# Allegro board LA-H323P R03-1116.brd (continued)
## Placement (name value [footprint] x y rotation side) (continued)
LED2  LTW-110DC5-C_WHITE  [LED_LTW-110DC5-C_3P]  4.7 93.03 270 bottom
LK1  TAI-TECH HCB1005KF-221T15 040  [MURAT_BLM15BD601SN1D_2P]  166.73 30.75 270 top
LK2  TAI-TECH HCB1005KF-221T15 0402  [MURAT_BLM15BD601SN1D_2P]  164.7 30.87 270 top
LL2  2.2UH +-20% 1239AS-H-2R2M=P2 2A  [TAI-T_HPC252012F-1R0Y_2P]  37.95 103.45 0 bottom
LM3  DLM0NSN900HY2D_4P  [MURAT_DLM0NSN900HY2D_4P]  219.49 36.93 90 top
LM5  DLM0NSN900HY2D_4P  [MURAT_DLM0NSN900HY2D_4P]  217.67 36.93 90 top
LM6  DLM0NSN900HY2D_4P  [MURAT_DLM0NSN900HY2D_4P]  255.75 19.51 0 bottom
LM7  DLM0NSN900HY2D_4P  [MURAT_DLM0NSN900HY2D_4P]  24.92 99.33 180 bottom
LV5  PBY160808T-300Y-N 0603  [MURAT_BLM18PG300SN1D_2P]  126.27 99.16 270 top
LV6  CHILISIN PBY160808T-301Y-N 0603  [KC_FBMA-L11160808601LMA10T_2P]  126.35 95.41 270 bottom
LV7  PBY160808T-300Y-N 0603  [MURAT_BLM18PG300SN1D_2P]  130.92 111.79 90 bottom
NOREF  -  []  69.24 66.72 90 top
NOREF#2  -  []  70.38 -26.74 0 top
NOREF#3  -  []  6.7 30.8 0 top
NOREF#4  -  []  102.2 108.8 0 top
NOREF#5  -  []  58.15 52.45 0 top
NOREF#6  -  []  253.17 11.8 0 top
NOREF#7  -  []  13.7 102.45 0 top
NOREF#8  -  []  136.74 81.27 0 top
NOREF#9  -  []  256.7 3.2 0 top
NOREF#10  -  []  -105.58 114.79 0 top
NOREF#11  -  []  136.74 49.47 0 top
NOREF#12  -  []  198.8 119.6 0 top
NOREF#13  -  []  125.34 112.32 0 top
NOREF#14  -  []  165.06 97.68 0 top
NOREF#15  -  []  94.03 81.27 0 top
NOREF#16  -  []  4.26 20.32 0 top
NOREF#17  -  []  94.03 49.47 0 top
NOREF#18  -  []  28.09 95.12 0 top
NOREF#19  -  []  119.34 139.17 180 bottom
NOREF#20  -  []  201.87 129.36 180 bottom
NOREF#21  -  []  82.06 40.56 90 bottom
PC1  0.022U_0402_25V7K  [C_0402]  213.72 31.5 90 bottom
PC2  1000P_0402_50V7K  [C_0402]  212.83 31.5 90 bottom
PC3  100P_0402_50V8J  [C_0402]  213.7 28.49 180 bottom
PC4  1000P_0402_50V7K  [C_0402]  213.7 27.6 180 bottom
PC5  100P_0402_50V8J  [C_0402]  210.45 27.82 270 bottom
PC6  1000P_0402_50V7K  [C_0402]  211.34 27.82 270 bottom
PC8  1000P_0402_50V7K  [C_0402]  117.08 28.9 90 bottom
PC9  0.01UF_0402_25V7K  [C_0402]  122.66 26.89 270 bottom
PC10  100P_0402_50V8J  [C_0402]  116.19 28.9 90 bottom
PC11  100P_0402_50V8J  [C_0402]  121.78 26.89 270 bottom
PC301  22U_0603_6.3V6M  [C_0603]  171.88 103.91 180 bottom
PC302  0.1U_0402_25V6  [C_0402]  186.8 119.44 270 bottom
PC303  0.1U_0402_25V6  [C_0402]  191.16 117.57 270 top
PC304  2200P_0402_50V7K  [C_0402]  192.05 117.57 270 top
PC305  10U_0603_25V6M  [C_0603]  191.68 117.94 270 bottom
PC306  22U_0603_6.3V6M  [C_0603]  177.44 112.13 270 bottom
PC307  22U_0603_6.3V6M  [C_0603]  178.71 112.13 270 bottom
PC308  22U_0603_6.3V6M  [C_0603]  181.25 112.13 270 bottom
PC309  22U_0603_6.3V6M  [C_0603]  179.98 112.13 270 bottom
PC310  4.7U_0402_6.3V6M  [C_0402]  186.11 112.17 270 bottom
PC311  680P_0402_50V7K  [C_0402]  181.74 118.96 90 bottom
PC312  1000P_0402_50V7K  [C_0402]  188.07 111.35 180 bottom
PC313  0.1U_0402_25V6  [C_0402]  182.76 108.97 180 bottom
PC314  10U_0603_25V6M  [C_0603]  187.69 105.62 270 bottom
PC315  10U_0603_25V6M  [C_0603]  188.96 105.62 270 bottom
PC316  2200P_0402_50V7K  [C_0402]  190.09 105.26 270 bottom
PC317  0.1U_0402_25V6  [C_0402]  190.98 105.26 270 bottom
PC318  2.2U_0402_6.3V6M  [C_0402]  181.85 102.46 270 bottom
PC319  22U_0603_6.3V6M  [C_0603]  171.88 101.42 180 bottom
PC322  22U_0603_6.3V6M  [C_0603]  171.88 105.18 180 bottom
PC323  22U_0603_6.3V6M  [C_0603]  171.88 106.37 180 bottom
PC324  680P_0402_50V7K  [C_0402]  181.39 102.94 0 top
PC325  4.7U_0402_6.3V6M  [C_0402]  183.57 100.6 180 bottom
PC326  1000P_0402_25V8J  [C_0402]  185.71 100.26 0 bottom
PC327  4.7U_0402_6.3V6M  [C_0402]  189.21 112.24 270 bottom
PC328  22U_0603_6.3V6M  [C_0603]  171.88 102.64 180 bottom
PC329  22U_0603_6.3V6M  [C_0603]  171.88 107.59 180 bottom
PC330  22U_0603_6.3V6M  [C_0603]  171.88 108.86 180 bottom
PC331  1U_0402_25V6K  [C_0402]  192.44 111.78 0 bottom
PC1001  10U_0603_25V6M  [C_0603]  191.7 97.16 270 bottom
PC1003  2200P_0402_50V7K  [C_0402]  190.6 96.92 270 bottom
PC1004  0.1U_0402_25V6  [C_0402]  189.71 96.88 270 bottom
PC1005  0.1U_0402_25V7K  [C_0402]  192.22 91.38 270 bottom
PC1006  1U_0201_6.3V6M  [C_0201]  185.74 91.59 270 bottom
PC1007  0.1U_0402_25V6  [C_0402]  184.57 97.97 180 bottom
PC1008  2.2U_0402_6.3V6M  [C_0402]  184.32 91.89 270 bottom
PC1009  680P_0402_50V7K  [C_0402]  183.66 92.13 180 top
PC1010  330P_0402_50V7K  [C_0402]  186.53 90.54 0 bottom
PC1011  22U_0603_6.3V6M  [C_0603]  175.18 91.7 180 bottom
PC1012  22U_0603_6.3V6M  [C_0603]  174.99 97.87 90 bottom
PC1013  22U_0603_6.3V6M  [C_0603]  175.18 90.48 180 bottom
PC1014  22U_0603_6.3V6M  [C_0603]  176.2 99.23 0 bottom
PC1016  1U_0201_6.3V6M  [C_0201]  185.11 91.59 270 bottom
PC1801  22U_0603_6.3V6M  [C_0603]  178.54 86.06 90 bottom
PC1802  68P_0402_50V8J  [C_0402]  183.83 88.09 180 bottom
PC1803  22U_0603_6.3V6M  [C_0603]  184.36 81.87 90 bottom
PC1804  22U_0603_6.3V6M  [C_0603]  183.14 81.87 90 bottom
PC1805  .1U_0402_16V7K  [C_0402]  182.91 86.32 0 bottom
PC1806  680P_0402_50V7K  [C_0402]  178.54 84.14 90 bottom
PC2501  22U_0603_6.3V6M  [C_0603]  2.84 47.96 0 bottom
PC2502  .1U_0402_16V7K  [C_0402]  7.4 42.82 0 bottom
PC2503  680P_0402_50V7K  [C_0402]  2.9 44.14 90 bottom
PC2504  68P_0402_50V8J  [C_0402]  8.31 47.14 180 bottom
PC2505  22U_0603_6.3V6M  [C_0603]  6.84 40.34 90 bottom
PC2506  22U_0603_6.3V6M  [C_0603]  8.11 40.34 90 bottom
PC2507  .1U_0402_16V7K  [C_0402]  5.51 47.57 90 bottom
PCA1  2.2U_0402_16V6K  [C_0402]  166.04 53.56 270 bottom
PCA2  2200P_0402_50V7K  [C_0402]  164.7 56.87 270 top
PCA3  0.1U_0402_25V6  [C_0402]  167.64 58.76 180 bottom
PCA4  10U_0603_25V6M  [C_0603]  163.75 57.11 270 bottom
PCA5  10U_0603_25V6M  [C_0603]  164.96 57.11 270 bottom
PCA6  0.1U_0402_25V6  [C_0402]  163.69 56.87 270 top
PCA7  0.1U_0402_25V6  [C_0402]  204.71 74.39 270 bottom
PCA8  680P_0402_50V7K  [C_0402]  162.16 55.47 270 top
PCB1  0.1U_0402_25V6  [C_0402]  195.43 60.86 180 bottom
PCB4  2200P_0402_50V7K  [C_0402]  183.24 51.38 90 top
PCB5  0.1U_0402_25V6  [C_0402]  185.48 54.63 180 top
PCB6  10U_0603_25V6M  [C_0603-S3]  179.13 54.35 0 bottom
PCB7  10U_0603_25V6M  [C_0603-S3]  179.13 55.56 0 bottom
PCB8  2200P_0402_50V7K  [C_0402]  181.14 51.56 270 top
PCB9  0.01UF_0402_25V7K  [C_0402]  177.35 56.47 270 top
PCB10  0.1U_0402_25V6  [C_0402]  195.43 59.97 180 bottom
PCB11  0.1U_0402_25V6  [C_0402]  193.57 59.89 90 bottom
PCB12  0.047U_0402_25V7K  [C_0402]  191.03 57.76 270 bottom
PCB13  1U_0402_25V6K  [C_0402]  191.1 58.95 0 bottom
PCB14  1U_0402_25V6K  [C_0402]  193.41 53.46 270 bottom
PCB15  10U_0603_25V6M  [C_0603-S3]  176.13 57.83 90 bottom
PCB16  10U_0603_25V6M  [C_0603-S3]  174.86 57.83 90 bottom
PCB17  0.1U_0402_25V6  [C_0402]  194.29 50.87 90 bottom
PCB18  0.1U_0402_25V6  [C_0402]  198.36 50.87 90 bottom
PCB19  680P_0402_50V7K  [C_0402]  176.72 51.33 180 top
PCB20  .1U_0402_16V7K  [C_0402]  195.75 50.84 0 bottom
PCB21  0.01UF_0402_25V7K  [C_0402]  199.31 54.89 0 bottom
PCB22  0.22U_0402_16V7K  [C_0402]  199.21 58.45 0 bottom
PCB23  100P_0402_50V8J  [C_0402]  199.21 57.56 0 bottom
PCB24  0.1U_0402_25V6  [C_0402]  147.2 34.56 0 bottom
PCB25  0.1U_0402_25V6  [C_0402]  182.05 51.56 270 top
PCG1  2.2U_0402_16V6K  [C_0402]  172.45 87.32 90 bottom
PCG2  0.1U_0402_25V6  [C_0402]  165.97 88.11 270 bottom
PCG4  2200P_0402_50V7K  [C_0402]  166.18 79.4 180 top
PCG5  10U_0603_25V6M  [C_0603]  166.04 78.38 180 bottom
PCG8  0.1U_0402_25V6  [C_0402]  195.74 76.55 270 top
PCG9  680P_0402_50V7K  [C_0402]  158.22 79.6 270 top
PCG10  10U_0603_25V6M  [C_0603]  166.04 77.11 180 bottom
PCG12  0.1U_0402_25V6  [C_0402]  166.18 78.38 180 top
PCM1  2200P_0402_50V7K  [C_0402]  2.51 66.4 270 bottom
PCM2  10U_0603_25V6M  [C_0603]  5.15 69.64 90 bottom
PCM3  1U_0201_6.3V6M  [C_0201]  11.73 76.31 90 bottom
PCM4  0.1U_0402_25V7K  [C_0402]  10.88 70.97 90 bottom
PCM5  10U_0402_6.3V6M  [C_0402]  7.55 72.03 180 bottom
PCM6  10U_0402_6.3V6M  [C_0402]  5.13 73.25 270 bottom
PCM7  1U_0201_6.3V6M  [C_0201]  12.66 74.19 180 bottom
PCM8  22U_0603_6.3V6M  [C_0603]  12.17 59.52 270 bottom
PCM9  22U_0603_6.3V6M  [C_0603]  13.44 59.52 270 bottom
PCM10  22U_0603_6.3V6M  [C_0603]  10.9 59.52 270 bottom
PCM11  22U_0603_6.3V6M  [C_0603]  5.63 61.36 180 bottom
PCM12  22U_0603_6.3V6M  [C_0603]  9.63 59.52 270 bottom
PCM13  22U_0603_6.3V6M  [C_0603]  5.63 60.09 180 bottom
PCM14  680P_0402_50V7K  [C_0402]  4.68 66.14 270 top
PCM15  0.033U_0402_16V7K  [C_0402]  6.17 75.54 180 bottom
PCM16  1U_0201_6.3V6M  [C_0201]  12.87 76.31 90 bottom
PCM17  0.1U_0402_10V7K  [C_0402]  9.25 78.43 90 bottom
PCM18  0.1U_0402_10V7K  [C_0402]  7.48 78.43 90 bottom
PCM19  1U_0201_6.3V6M  [C_0201]  12.3 76.31 90 bottom
PCM20  1U_0201_6.3V6M  [C_0201]  12.66 74.76 180 bottom
PCM21  1U_0201_6.3V6M  [C_0201]  12.66 75.33 180 bottom
PCV1  .1U_0402_16V7K  [C_0402]  124.87 136.67 0 top
PCV2  33U_25V_NC_6.3X4.5  [C_6P3X4P5]  109.58 117.24 0 bottom
PCV3  33U_25V_NC_6.3X4.5  [C_6P3X4P5]  109.58 110.26 0 bottom
PCV5  10U_0603_25V6M  [C_0603-S3]  111.04 126.89 0 bottom
PCV6  10U_0603_25V6M  [C_0603-S3]  111.04 126.89 0 top
PCV9  2200P_0402_50V7K  [C_0402]  111.54 128.04 0 bottom
PCV10  0.1U_0402_25V6  [C_0402]  111.54 128.04 0 top
PCV11  680P_0402_50V7K  [C_0402]  115.1 125.5 0 top
PCV12  0.01U_0402_16V7K  [C_0402]  122.36 139.21 180 bottom
PCV13  2700P_0402_50V7K  [C_0402]  119.24 140.43 270 top
PCV14  0.1U_0402_25V6  [C_0402]  125.55 132.2 180 top
PCV15  10U_0603_25V6M  [C_0603-S3]  108.19 131.53 90 bottom
PCV16  10U_0603_25V6M  [C_0603-S3]  108.19 131.53 90 top
PCV18  0.01U_0402_16V7K  [C_0402]  117.38 137.94 0 top
PCV19  2200P_0402_50V7K  [C_0402]  109.29 131.95 90 bottom
PCV20  0.1U_0402_25V6  [C_0402]  109.29 131.95 90 top
PCV21  0.1U_0402_25V6  [C_0402]  121.09 139.85 180 top
PCV22  2.2U_0402_16V6K  [C_0402]  121.03 132.29 270 top
PCV24  0.1U_0402_25V6  [C_0402]  119.95 132.86 180 top
PCV25  680P_0402_50V7K  [C_0402]  116.14 129.43 180 top
PCV26  1000P_0402_50V7K  [C_0402]  118.3 138.83 180 top
PCV28  1U_0201_6.3V6M  [C_0201]  144.42 103.27 180 top
PCV29  1U_0201_6.3V6M  [C_0201]  145.66 95.84 0 top
PCV30  1U_0201_6.3V6M  [C_0201]  144.42 103.91 180 top
PCV31  1U_0201_6.3V6M  [C_0201]  145.66 96.41 0 top
PCV32  1U_0201_6.3V6M  [C_0201]  142.4 104.33 270 top
PCV34  330U_D1_2VY_R9M  [C_X]  115.3 115.46 180 top
PCV35  560U_D2_2VM_R4.5M  [C_X]  125.79 125.36 180 top
PCV37  4.7U_0402_6.3V6M  [C_0402]  147.16 105.46 0 top
PCV38  4.7U_0402_6.3V6M  [C_0402]  140.8 103.53 0 top
PCV39  4.7U_0402_6.3V6M  [C_0402]  145.5 97.18 0 top
PCV40  4.7U_0402_6.3V6M  [C_0402]  141.46 96.6 180 top
PCV41  4.7U_0402_6.3V6M  [C_0402]  141.46 98.51 180 top
PCV42  4.7U_0402_6.3V6M  [C_0402]  141.46 99.46 180 top
PCV43  4.7U_0402_6.3V6M  [C_0402]  143.87 96.29 180 top
PCV44  4.7U_0402_6.3V6M  [C_0402]  149.38 106.33 270 top
PCV45  4.7U_0402_6.3V6M  [C_0402]  146.34 107.5 180 top
PCV46  4.7U_0402_6.3V6M  [C_0402]  144.06 105.48 180 top
PCV47  4.7U_0402_6.3V6M  [C_0402]  146.32 105.46 180 top
PCV48  4.7U_0402_6.3V6M  [C_0402]  141.46 97.56 180 top
PCV49  4.7U_0402_6.3V6M  [C_0402]  143.72 97.94 0 top
PCV50  4.7U_0402_6.3V6M  [C_0402]  142.4 99.41 90 top
PCV51  4.7U_0402_6.3V6M  [C_0402]  142.4 101.16 90 top
PCV52  22U_0603_6.3V6M  [C_0603]  141.83 105.62 180 top
PCV53  47U_0805_6.3V6M  [C_0805]  142.08 107.54 180 top
PCV56  4.7U_0402_6.3V6M  [C_0402]  144.29 99.75 180 top
PCV57  4.7U_0402_6.3V6M  [C_0402]  147.18 107.5 0 top
PCV58  22U_0603_6.3V6M  [C_0603]  144.55 107.53 180 top
PCV59  22U_0603_6.3V6M  [C_0603]  119.11 111.27 180 top
PCV60  22U_0603_6.3V6M  [C_0603]  119.11 116.1 180 top
PCV61  22U_0603_6.3V6M  [C_0603]  119.11 117.3 180 top
PCV66  10U_0603_6.3V6M  [C_0603]  119.11 117.3 180 bottom
PCV67  10U_0603_6.3V6M  [C_0603]  119.11 114.89 180 top
PCV68  10U_0603_6.3V6M  [C_0603]  119.11 113.69 180 top
PCV69  10U_0603_6.3V6M  [C_0603]  119.11 110.07 180 top
PCV70  10U_0603_6.3V6M  [C_0603]  119.11 113.69 180 bottom
PCV71  10U_0603_6.3V6M  [C_0603]  119.11 112.48 180 bottom
PCV72  10U_0603_6.3V6M  [C_0603]  119.11 111.27 180 bottom
PCV73  10U_0603_6.3V6M  [C_0603]  119.11 110.07 180 bottom
PCV74  10U_0603_6.3V6M  [C_0603]  119.11 116.1 180 bottom
PCV75  10U_0603_6.3V6M  [C_0603]  119.11 114.89 180 bottom
PCV76  10U_0603_6.3V6M  [C_0603]  119.11 112.48 180 top
PCW1  1U_0201_6.3V6M  [C_0201]  191.82 132.77 270 bottom
PCW2  0.1U_0402_25V6  [C_0402]  191.85 139.09 270 top
PCW3  2200P_0402_50V7K  [C_0402]  192.74 139.09 270 top
PCW4  1U_0201_6.3V6M  [C_0201]  192.45 132.77 270 bottom
PCW5  10U_0603_25V6M  [C_0603]  190.45 139.15 270 bottom
PCW6  0.1U_0402_25V6  [C_0402]  185.58 139.72 270 bottom
PCW7  680P_0402_50V7K  [C_0402]  183.24 136.55 0 top
PCW8  1U_0201_6.3V6M  [C_0201]  185.53 132.77 270 bottom
PCW9  2.2U_0402_6.3V6M  [C_0402]  184.02 133.81 180 bottom
PCW10  330P_0402_50V7K  [C_0402]  186.97 131.97 0 bottom
PCW11  22U_0603_6.3V6M  [C_0603]  174.43 134.87 180 bottom
PCW12  22U_0603_6.3V6M  [C_0603]  174.43 136.14 180 bottom
PCW13  22U_0603_6.3V6M  [C_0603]  174.43 138.68 180 bottom
PCW14  22U_0603_6.3V6M  [C_0603]  174.43 137.41 180 bottom
PCW16  1U_0201_6.3V6M  [C_0201]  186.16 132.77 270 bottom
PCW17  10U_0603_25V6M  [C_0603]  191.72 139.15 270 bottom
PCW18  22U_0603_6.3V6M  [C_0603]  174.43 141.22 180 bottom
PCW19  22U_0603_6.3V6M  [C_0603]  174.43 139.95 180 bottom
PCZ1  10U_0603_25V6M  [C_0603]  171.43 68.55 0 bottom
PCZ3  0.1U_0402_25V6  [C_0402]  206.56 73.55 180 bottom
PCZ4  0.47U_0402_25V6K  [C_0402]  200.59 74.7 180 top
PCZ5  470P_0402_50V7K  [C_0402]  204.78 69.24 180 bottom
PCZ6  68P_0402_50V8J  [C_0402]  203.94 70.94 90 bottom
PCZ7  0.1U_0402_10V6K  [C_0402]  201.21 70.45 270 top
PCZ9  0.1U_0402_10V6K  [C_0402]  202.04 65.73 90 bottom
PCZ11  390P_0402_50V7K  [C_0402]  201.02 63.82 90 bottom
PCZ12  56P_0402_50V8  [C_0402]  200.97 66.57 180 bottom
PCZ13  0.1U_0402_25V6  [C_0402]  198.48 65.73 90 bottom
PCZ15  0.47U_0402_25V6K  [C_0402]  198.23 75.66 270 top
PCZ16  0.1U_0402_25V6  [C_0402]  193.2 65.81 0 top
PCZ18  0.1U_0402_25V6  [C_0402]  197.21 75.66 270 top
PCZ19  0.1U_0402_25V6  [C_0402]  193.35 69.42 270 bottom
PCZ20  82P_0402_50V8J  [C_0402]  194.42 77.16 90 bottom
PCZ21  270P_0402_50V7K  [C_0402]  195.36 77.24 0 bottom
PCZ23  4.7U_0402_10V6M  [C_0402]  192.78 70.42 90 bottom
PCZ26  33U_25V_NC_6.3X4.5  [C_6P3X4P5]  174.35 75.46 270 bottom
PCZ28  0.1U_0402_25V6  [C_0402]  171.43 66.07 270 bottom
PCZ29  0.1U_0402_25V6  [C_0402]  167.95 68.73 180 top
PCZ30  2200P_0402_50V7K  [C_0402]  167.95 70 180 top
PCZ31  10U_0603_25V6M  [C_0603]  168.19 70 180 bottom
PCZ32  10U_0603_25V6M  [C_0603]  168.19 68.73 180 bottom
PCZ33  2200P_0402_50V7K  [C_0402]  167.95 66.19 180 top
PCZ34  10U_0603_25V6M  [C_0603]  168.19 67.46 180 bottom
PCZ35  0.1U_0402_25V6  [C_0402]  171.5 62.2 270 bottom
PCZ36  0.1U_0402_25V6  [C_0402]  167.95 67.46 180 top
PCZ37  10U_0603_25V6M  [C_0603]  168.19 66.19 180 bottom
PCZ40  2.2U_0402_16V6K  [C_0402]  178.2 64.62 90 bottom
PCZ41  2.2U_0402_16V6K  [C_0402]  178.21 62.12 180 bottom
PCZ42  0.1U_0402_25V6  [C_0402]  196.25 65.93 0 bottom
PCZ43  0.1U_0402_25V6  [C_0402]  195.82 65.88 270 top
PCZ44  680P_0402_50V7K  [C_0402]  165.34 71.85 270 top
PCZ45  680P_0402_50V7K  [C_0402]  161.4 64.59 90 top
PCZ47  10U_0603_25V6M  [C_0603]  178.42 73.81 270 bottom
PCZ68  330U_D1_2VY_R9M  [C_D1]  147.05 67.28 270 bottom
PCZ69  330U_D1_2VY_R9M  [C_D1]  149.92 88.03 180 bottom
PCZ70  22U_0603_6.3V6M  [C_0603]  132 72.92 90 top
PCZ71  22U_0603_6.3V6M  [C_0603]  124.48 71.86 270 top
PCZ72  22U_0603_6.3V6M  [C_0603]  130.21 76.75 270 top
PCZ73  22U_0603_6.3V6M  [C_0603]  114.64 71.42 270 top
PCZ74  22U_0603_6.3V6M  [C_0603]  145.4 81.24 90 bottom
PCZ75  22U_0603_6.3V6M  [C_0603]  115.91 71.42 270 top
PCZ76  22U_0603_6.3V6M  [C_0603]  142.86 80.22 270 bottom
PCZ77  22U_0603_6.3V6M  [C_0603]  117.18 71.42 270 top
PCZ78  22U_0603_6.3V6M  [C_0603]  114.92 60.64 270 top
PCZ79  22U_0603_6.3V6M  [C_0603]  130.11 68.03 270 top
PCZ80  22U_0603_6.3V6M  [C_0603]  131.33 68.02 270 top
PCZ81  22U_0603_6.3V6M  [C_0603]  113.7 60.64 270 top
PCZ82  22U_0603_6.3V6M  [C_0603]  116.14 60.64 270 top
PCZ85  22U_0603_6.3V6M  [C_0603]  146.67 81.24 90 bottom
PCZ86  22U_0603_6.3V6M  [C_0603]  132 76.73 270 top
PCZ87  22U_0603_6.3V6M  [C_0603]  119.81 55.26 180 top
PCZ88  22U_0603_6.3V6M  [C_0603]  115.99 56.88 90 top
PCZ89  22U_0603_6.3V6M  [C_0603]  117.28 56.88 90 top
PCZ90  22U_0603_6.3V6M  [C_0603]  118.6 56.92 90 top
PCZ91  22U_0603_6.3V6M  [C_0603]  119.81 56.92 90 top
PCZ93  22U_0603_6.3V6M  [C_0603]  149.72 57.36 90 bottom
PCZ94  22U_0603_6.3V6M  [C_0603]  147.18 57.36 90 bottom
PCZ95  22U_0603_6.3V6M  [C_0603]  150.99 57.36 90 bottom
PCZ96  22U_0603_6.3V6M  [C_0603]  148.45 57.36 90 bottom
PCZ97  22U_0603_6.3V6M  [C_0603]  125.13 62.86 270 top
PCZ98  22U_0603_6.3V6M  [C_0603]  127.67 63 270 top
PCZ99  22U_0603_6.3V6M  [C_0603]  131.35 62.36 270 top
PCZ100  22U_0603_6.3V6M  [C_0603]  117.39 60.64 270 top
PCZ101  22U_0603_6.3V6M  [C_0603]  130.13 62.36 270 top
PCZ102  22U_0603_6.3V6M  [C_0603]  130.75 63.8 90 top
PCZ103  22U_0603_6.3V6M  [C_0603]  128.91 62.36 270 top
PCZ104  22U_0603_6.3V6M  [C_0603]  132 64.22 90 top
PCZ109  22U_0603_6.3V6M  [C_0603]  116.31 72.94 90 top
PCZ110  22U_0603_6.3V6M  [C_0603]  113.39 75.33 90 top
PCZ111  22U_0603_6.3V6M  [C_0603]  114.66 76.73 270 top
PCZ112  22U_0603_6.3V6M  [C_0603]  116.3 75.35 90 top
PCZ113  22U_0603_6.3V6M  [C_0603]  130.67 72.92 90 top
PCZ114  22U_0603_6.3V6M  [C_0603]  128.13 72.92 90 top
PCZ115  22U_0603_6.3V6M  [C_0603]  144.13 80.22 270 bottom
PCZ116  22U_0603_6.3V6M  [C_0603]  145.4 83.65 90 bottom
PCZ117  22U_0603_6.3V6M  [C_0603]  145.4 80.22 270 bottom
PCZ119  22U_0603_6.3V6M  [C_0603]  121.01 56.61 90 top
PCZ127  22U_0603_6.3V6M  [C_0603]  127.02 63.96 90 top
PCZ131  22U_0603_6.3V6M  [C_0603]  129 76.76 270 top
PCZ132  22U_0603_6.3V6M  [C_0603]  129.4 72.92 90 top
PCZ134  22U_0603_6.3V6M  [C_0603]  114.66 74.31 270 top
PCZ135  22U_0603_6.3V6M  [C_0603]  113.39 73.43 270 top
PCZ136  22U_0603_6.3V6M  [C_0603]  125.69 71.86 270 top
PCZ137  22U_0603_6.3V6M  [C_0603]  144.13 83.65 90 bottom
PCZ140  1U_0201_6.3V6M  [C_0201]  112.54 57.39 180 top
PCZ141  1U_0201_6.3V6M  [C_0201]  112.54 56.8 180 top
PCZ142  1U_0201_6.3V6M  [C_0201]  121.99 55.66 90 top
PCZ143  1U_0201_6.3V6M  [C_0201]  112.54 57.94 180 top
PCZ144  1U_0201_6.3V6M  [C_0201]  118.77 56.15 180 top
PCZ145  1U_0201_6.3V6M  [C_0201]  121.9 57.58 90 top
PCZ146  1U_0201_6.3V6M  [C_0201]  120.95 55.56 270 top
PCZ150  22U_0603_6.3V6M  [C_0603]  144.06 63.33 270 bottom
PCZ154  22U_0603_6.3V6M  [C_0603]  118.26 67.23 90 top
PCZ155  22U_0603_6.3V6M  [C_0603]  119.47 67.23 90 top
PCZ157  22U_0603_6.3V6M  [C_0603]  117.94 75.37 90 top
PCZ158  22U_0603_6.3V6M  [C_0603]  119.62 76.77 270 top
PCZ159  22U_0603_6.3V6M  [C_0603]  142.86 83.65 90 bottom
PCZ160  22U_0603_6.3V6M  [C_0603]  142.86 81.24 90 bottom
PCZ161  22U_0603_6.3V6M  [C_0603]  144.13 81.24 90 bottom
PCZ162  22U_0603_6.3V6M  [C_0603]  146.67 83.65 90 bottom
PCZ163  22U_0603_6.3V6M  [C_0603]  146.67 80.22 270 bottom
PCZ164  22U_0603_6.3V6M  [C_0603]  117.94 72.92 90 top
PCZ165  22U_0603_6.3V6M  [C_0603]  119.62 74.34 270 top
PCZ166  22U_0603_6.3V6M  [C_0603]  121.18 73.95 90 top
PCZ167  1U_0201_6.3V6M  [C_0201]  112.35 66.74 90 top
PCZ168  1U_0201_6.3V6M  [C_0201]  112.99 66.74 90 top
PCZ169  1U_0201_6.3V6M  [C_0201]  112.8 65.74 270 top
PCZ170  1U_0201_6.3V6M  [C_0201]  112.16 65.74 270 top
PCZ171  1U_0201_6.3V6M  [C_0201]  119.54 60.21 270 top
PCZ172  1U_0201_6.3V6M  [C_0201]  118.91 60.21 270 top
PCZ173  1U_0201_6.3V6M  [C_0201]  123.54 62.14 90 top
PCZ174  1U_0201_6.3V6M  [C_0201]  126.3 61.89 90 top
PCZ175  1U_0201_6.3V6M  [C_0201]  118.27 60.21 270 top
PCZ176  1U_0201_6.3V6M  [C_0201]  120.86 59.98 90 top
PCZ177  1U_0201_6.3V6M  [C_0201]  121.37 72.33 90 top
PCZ178  1U_0201_6.3V6M  [C_0201]  121.94 72.33 90 top
PCZ179  1U_0201_6.3V6M  [C_0201]  112.35 75.13 90 top
PCZ180  1U_0201_6.3V6M  [C_0201]  120.8 72.33 90 top
PCZ181  1U_0201_6.3V6M  [C_0201]  120.85 87.35 90 top
PCZ182  1U_0201_6.3V6M  [C_0201]  121.45 87.35 90 top
PCZ183  1U_0201_6.3V6M  [C_0201]  120.48 71.33 270 top
PCZ184  1U_0201_6.3V6M  [C_0201]  118.47 87.36 90 top
PCZ185  1U_0201_6.3V6M  [C_0201]  119.06 87.36 90 top
PCZ186  1U_0201_6.3V6M  [C_0201]  119.66 87.36 90 top
PCZ187  1U_0201_6.3V6M  [C_0201]  124.15 64.97 270 top
PCZ188  1U_0201_6.3V6M  [C_0201]  119.12 70 270 top
PCZ189  1U_0201_6.3V6M  [C_0201]  111.74 66.74 90 top
PCZ190  1U_0201_6.3V6M  [C_0201]  112.76 60.57 270 top
PCZ191  1U_0201_6.3V6M  [C_0201]  112.24 62.96 0 top
PCZ192  1U_0201_6.3V6M  [C_0201]  112.19 64.49 0 top
PCZ193  1U_0201_6.3V6M  [C_0201]  143.18 68.32 270 bottom
PCZ194  1U_0201_6.3V6M  [C_0201]  142.54 68.32 270 bottom
PCZ195  1U_0201_6.3V6M  [C_0201]  122.73 62.73 270 top
PCZ196  1U_0201_6.3V6M  [C_0201]  120.86 59.38 270 top
PCZ197  1U_0201_6.3V6M  [C_0201]  120.63 76.75 0 top
PCZ198  1U_0201_6.3V6M  [C_0201]  120.25 87.35 90 top
PCZ199  1U_0201_6.3V6M  [C_0201]  120.63 76.12 0 top
PCZ200  1U_0201_6.3V6M  [C_0201]  113.62 66.74 90 top
PCZ201  1U_0201_6.3V6M  [C_0201]  118.08 70.47 270 top
PCZ202  1U_0201_6.3V6M  [C_0201]  120.26 59.68 270 top
PCZ203  1U_0201_6.3V6M  [C_0201]  124.15 61.89 270 top
PCZ204  1U_0201_6.3V6M  [C_0201]  122.16 59.95 270 top
PCZ205  1U_0201_6.3V6M  [C_0201]  109.23 65.08 90 top
PCZ206  1U_0201_6.3V6M  [C_0201]  112.2 63.9 0 top
PCZ207  1U_0201_6.3V6M  [C_0201]  125.62 59.23 180 top
PCZ208  1U_0201_6.3V6M  [C_0201]  124.16 62.54 90 top
PCZ209  1U_0201_6.3V6M  [C_0201]  112.21 61.56 0 top
PCZ210  1U_0201_6.3V6M  [C_0201]  121.24 69.54 90 top
PCZ211  1U_0201_6.3V6M  [C_0201]  120.67 69.54 90 top
PCZ212  1U_0201_6.3V6M  [C_0201]  121.88 67.39 270 top
PCZ213  1U_0201_6.3V6M  [C_0201]  121.31 67.39 270 top
PCZ214  1U_0201_6.3V6M  [C_0201]  125.62 58.63 180 top
PCZ215  330U_D1_2VY_R9M  [C_D1]  144.57 70.05 90 bottom
PCZ227  0.1U_0402_25V6  [C_0402]  201.53 80.36 270 bottom
PCZ228  0.47U_0402_6.3V6K  [C_0402]  206.56 72.66 180 bottom
PCZ229  33U_25V_NC_6.3X4.5  [C_6P3X4P5]  174.35 79.39 90 bottom
PCZ230  1U_0402_25V6K  [C_0402]  193.47 75.71 180 bottom
PCZ231  47P_0402_50V8J  [C_0402]  192.26 64.79 180 top
PCZ232  47P_0402_50V8J  [C_0402]  192.26 65.68 180 top
PCZ233  22U_0603_6.3V6M  [C_0603]  127.68 67.74 270 top
PCZ234  22U_0603_6.3V6M  [C_0603]  125.23 68.1 270 top
PCZ235  22U_0603_6.3V6M  [C_0603]  117.05 67.23 90 top
PCZ236  22U_0603_6.3V6M  [C_0603]  125.28 64.03 90 top
PCZ237  22U_0603_6.3V6M  [C_0603]  128.29 63.96 90 top
PCZ238  22U_0603_6.3V6M  [C_0603]  129.51 63.79 90 top
PCZ239  22U_0603_6.3V6M  [C_0603]  115.85 67.23 90 top
PCZ240  22U_0603_6.3V6M  [C_0603]  128.89 68.05 270 top
PCZ243  22U_0603_6.3V6M  [C_0603]  142.86 64.35 90 bottom
PCZ244  22U_0603_6.3V6M  [C_0603]  144.06 68.16 270 bottom
PCZ245  22U_0603_6.3V6M  [C_0603]  144.06 64.35 90 bottom
PCZ246  22U_0603_6.3V6M  [C_0603]  126.46 68.1 270 top
PCZ247  22U_0603_6.3V6M  [C_0603]  114.64 67.23 90 top
PCZ248  220U_D7_2VM_R4.5M  [C_D7]  120.78 63.63 180 top
PD1  -  [L30ESD24VC3-2_SOT23-3]  214.49 26.11 90 bottom
PD2  -  [L30ESD24VC3-2_SOT23-3]  210.37 31.66 0 bottom
PD3  LUDZS3.6BT1G_SOD323-2  [LUDZS3P6BT1G_SOD323-2]  209.03 25.67 0 bottom
PDB1  -  [BAS40CW_SOT323-3]  180.93 61.81 270 bottom
PDB2  -  [RB751V-40_SOD323-2]  190.2 53.78 0 bottom
PH1  100K_0402_1%_B25/50 4250K  [R_0402]  132.32 58.26 270 top
PHA1  4.7K_0402_5%_ERTJ0ER472J  [R_0402]  156.27 52.85 180 bottom
PHG1  10K_0402_1%_B25/50 3370K  [R_0402]  153.86 85.88 180 bottom
PHZ1  100K_0402_1%_B25/50 4250K  [R_0402]  156.07 76.8 270 bottom
PHZ2  100K_0402_1%_B25/50 4250K  [R_0402]  164.27 70.12 180 bottom
PHZ3  100K_0402_1%_B25/50 4250K  [R_0402]  157.67 85.75 180 bottom
PJ302  -  [JUMP_43X118]  176.91 115.34 180 bottom
PJ303  -  [JUMP_43X39]  184.4 111.9 270 bottom
PJ305  -  [JUMP_43X118]  174.48 102.5 270 top
PJ1002  -  [JUMP_43X118]  177.02 91.21 270 top
PJ1801  JUMP_43X39  [JUMP_43X39_0805]  179.69 89.89 180 bottom
PJ1802  -  [JUMP_43X79]  182.99 80.2 270 bottom
PJ2501  JUMP_43X39  [JUMP_43X39_0805]  3.79 50.58 180 bottom
PJ2502  JUMP_43X39  [JUMP_43X39_0805]  4.3 38.7 180 bottom
PJM2  -  [JUMP_43X118]  6.33 58.1 270 bottom
PJM3  JUMP_43X39  [JUMP_43X39_0805]  3.54 73.76 180 bottom
PJP1  ACES_51483-00801-001  [ACES_51483-00801-001_8P-T]  222 24.45 0 bottom
PJPB1  OCTEK_BTJ-08TFBRZB  [OCTEK_BTJ-08TFBRZB_8P]  116.72 24.5 180 bottom
PJV1  -  [JUMP_43X79]  109.96 105.6 270 bottom
PJW1  -  [JUMP_43X79]  193.52 139.66 0 bottom
PJW2  -  [JUMP_43X118]  176.55 131.08 180 bottom
PL11  -  [5A_Z80_0805_2P]  215.12 30.97 270 bottom
PL12  -  [5A_Z80_0805_2P]  216.9 30.97 270 bottom
PL13  -  [5A_Z80_0805_2P]  119.02 31.39 0 bottom
PL14  -  [5A_Z80_0805_2P]  119.02 29.48 0 bottom
PL301  1UH_11A_20%_7X7X3_M  [L_7X7X3_M]  180.55 105.68 180 bottom
PL302  1.5UH_6A_20%_5X5X3_M  [L_5X5X3_M_2P]  184.37 115.56 180 bottom
PL303  3A_Z120_40M_0603_2P  [3A_Z120_0603_2P]  194.05 118.96 180 bottom
PL304  3A_Z120_40M_0603_2P  [3A_Z120_0603_2P]  194.05 117.5 180 bottom
PL305  -  [5A_Z80_0805_2P]  184.13 108.95 270 bottom
PL306  -  [5A_Z80_0805_2P]  186.04 108.95 270 bottom
PL1001  1UH_11A_20%_7X7X3_M  [L_7X7X3_M_2P]  182.46 94.86 180 bottom
PL1002  3A_Z120_40M_0603_2P  [3A_Z120_0603_2P]  194.66 97.4 180 bottom
PL1003  3A_Z120_40M_0603_2P  [3A_Z120_0603_2P]  194.66 98.92 180 bottom
PL1801  1UH_MHCD252012A-1R0M-A8S_3A_20%  [CHILI_MHCD252012A-1R0M-A8S_2P]  179.96 82.7 0 bottom
PL2501  1UH_MHCD252012A-1R0M-A8S_3A_20%  [CHILI_MHCD252012A-1R0M-A8S_2P]  4.81 42.42 270 bottom
PLA1  0.47UH_NA__12.2A_20%  [L_5X5X3_M]  157.86 56.28 180 bottom
PLB1  4.7UH_5.5A_20%_7X7X3_M  [VISHAY_IHLP-2525CZ-01_2P]  172.96 53.49 180 bottom
PLB11  1UH_2.8A_30%_4X4X2_F  [L_4X4X2_F_2P]  179.01 59.76 270 bottom
PLG1  0.24UH_22A_+-20%_7X7X3_M  [L_7X7X3_M]  155.28 81.74 180 bottom
PLM1  1UH_11A_20%_7X7X3_M  [L_7X7X3_M_2P]  10.32 62.02 90 bottom
PLM2  -  [5A_Z80_0805_2P]  3.36 70.91 270 bottom
PLV3  0.22UH_24A_20%_ 7X7X4_M  [L_7X7X4_M]  118.37 122.7 0 bottom
PLV4  0.22UH_24A_20%_ 7X7X4_M  [L_7X7X4_M]  118.88 130.7 0 bottom
PLW1  1UH_11A_20%_7X7X3_M  [L_7X7X3_M_2P]  182.88 138.07 180 bottom
PLZ1  0.24UH_22A_+-20%_7X7X3_M  [L_7X7X3_M]  154.9 72.92 180 bottom
PLZ2  0.24UH_22A_+-20%_7X7X3_M  [L_7X7X3_M]  153.21 61.19 90 bottom
PLZ3  -  [5A_Z80_0805_2P]  178.58 75.2 0 bottom
PQ2  L2N7002SDW1T1G 2N SC88-6  [L2N7002DW1T1G_SC88-6]  179.65 68.79 180 bottom
PQA1  -  [AONH36334_DFN3X3A8-10]  160.42 57.81 0 bottom
PQB1  -  [AONH36334_DFN3X3A8-10]  178.66 52.88 0 bottom
PQB2  -  [2N7002KW_SOT323-3]  191.24 55.43 180 top
PQB11  AONS32306_N_DFN56-8-5  [Q_N_DFN56-8-5]  188.7 53.11 180 top
PQB12  -  [AON7506_DFN33-8-5]  187.21 54.97 0 top
PQB13  -  [AON7506_DFN33-8-5]  178.51 57.6 270 top
PQG1  -  [AON6380_DFN5X6-8-5]  164.14 80.16 90 bottom
PQG2  AON6314_N_DFN56-8-5  [Q_N_DFN56-8-5]  162.1 78.95 180 bottom
PQM1  -  [AONH36334_DFN3X3A8-10]  3.88 67.69 0 bottom
PQV1  -  [FDPC5030SG_POWERCLIP56-8-10]  109.74 121.69 90 bottom
PQV2  -  [FDPC5030SG_POWERCLIP56-8-10]  110.5 129.31 90 bottom
PQZ1  -  [AON6380_DFN5X6-8-5]  164.14 71.65 90 bottom
PQZ2  AON6314_N_DFN56-8-5  [Q_N_DFN56-8-5]  161.77 69.21 180 bottom
PQZ3  -  [AON6380_DFN5X6-8-5]  164.14 60.73 90 bottom
PQZ4  AON6314_N_DFN56-8-5  [Q_N_DFN56-8-5]  158.1 65.7 0 bottom
PR1  0_0402_5%  [R_0402]  218.8 29.81 270 top
PR2  100K_0402_5%  [R_0402]  219.69 29.81 270 top
PR3  10K_0402_1%  [R_0402]  208.64 27.82 0 bottom
PR4  750_0402_1%  [R_0402]  210.43 24.34 0 bottom
PR5  10K_0402_1%  [R_0402]  209.56 26.93 180 bottom
PR6  100K_0402_5%  [R_0402]  209.38 24.34 180 bottom
PR9  16.2K_0402_1%  [R_0402]  152.98 49.77 0 bottom
PR10  5.9K_0402_1%  [R_0402]  149.39 33.78 0 bottom
PR13  10K_0402_1%  [R_0402]  150.3 34.56 180 bottom
PR14  100_0402_5%  [R_0402]  96.08 24.86 90 bottom
PR15  100_0402_5%  [R_0402]  95.32 24.86 90 bottom
PR16  100K_0402_5%  [R_0402]  106.76 27.25 90 top
PR17  100_0402_5%  [R_0402]  107.65 27.25 90 top
PR18  0_0402_5%  [R0402_0OHM]  108.69 27.25 90 top
PR19  1.8K +-1% 0805  [R_0805]  181.81 72.16 180 bottom
PR20  470K_0402_5%  [R_0402]  178.19 67 90 bottom
PR21  1M_0402_5%  [R_0402]  178.95 67.91 270 bottom
PR301  2.2K_0402_5%  [R_0402]  191.63 111.32 90 bottom
PR302  0_0402_5%  [R0402_0OHM]  187.68 118.52 90 bottom
PR303  4.7_1206_5%  [R_1206]  185.58 119.5 180 bottom
PR304  100K_0402_5%  [R_0402]  193.35 114.19 180 bottom
PR305  1K_0402_1%  [R_0402]  187.16 112.21 0 bottom
PR306  0_0402_5%  [R0402_0OHM]  182.86 107.13 90 bottom
PR307  499K_0402_1%  [R_0402]  193.35 112.67 180 bottom
PR308  4.7_1206_5%  [R_1206]  181.85 106.76 270 top
PR309  150K_0402_1%  [R_0402]  192.44 113.43 0 bottom
PR310  0_0402_5%  [R_0402]  187.46 102.02 270 bottom
PR311  0_0402_5%  [R0402_0OHM]  190.86 111.32 90 bottom
PR312  1K_0402_1%  [R_0402]  186.62 99.4 180 bottom
PR313  1M_0402_1%  [R_0402]  190.1 112.24 270 bottom
PR1001  0_0402_5%  [R0402_0OHM]  190.62 93.7 270 bottom
PR1002  1M_0402_1%  [R_0402]  191.33 91.38 270 bottom
PR1003  0_0402_5%  [R0402_0OHM]  189.81 90.46 90 bottom
PR1004  0_0402_5%  [R_0402]  190.57 91.38 270 bottom
PR1005  100K_0402_1%  [R_0402]  189.77 93.61 90 bottom
PR1006  0_0402_5%  [R0402_0OHM]  186.29 97.96 180 bottom
PR1007  4.7_1206_5%  [R_1206]  183.13 96 270 top
PR1008  20K_0402_1%  [R_0402]  187.44 91.38 180 bottom
PR1009  24.9K_0402_1%  [R_0402]  189.02 91.38 270 bottom
PR1010  1K_0402_1%  [R_0402]  188.25 90.47 90 bottom
PR1801  100K_0402_5%  [R_0402]  181.92 88.41 180 bottom
PR1802  4.7_0603_5%  [R_0603]  178.7 81.74 90 bottom
PR1803  20K_0402_1%  [R_0402]  183.82 88.97 180 bottom
PR1804  0_0402_5%  [R0402_0OHM]  183.83 84.48 180 bottom
PR1805  1M_0402_1%  [R_0402]  182.91 85.43 0 bottom
PR1806  10K_0402_1%  [R_0402]  182.91 87.21 0 bottom
PR2501  0_0402_5%  [R0402_0OHM]  8.36 45.44 270 bottom
PR2502  0_0402_5%  [R_0402]  7.48 45.44 270 bottom
PR2503  1M_0402_1%  [R_0402]  7.4 43.71 0 bottom
PR2504  100K_0402_5%  [R_0402]  5.19 50.2 270 bottom
PR2505  4.7_0402_5%  [R_0402]  2.9 42.36 90 bottom
PR2506  32.4K_0402_1%  [R_0402]  8.31 46.25 180 bottom
PR2507  10K_0402_1%  [R_0402]  7.4 48.03 0 bottom
PRA1  1_0402_5%  [R_0402]  166.92 52.65 90 bottom
PRA2  2.2_0603_5%  [R_0603]  168.77 57.61 90 bottom
PRA4  4.7_1206_5%  [R_1206]  158.16 56.41 0 top
PRA6  523_0603_1%  [R_0603]  209.28 71.2 90 bottom
PRA7  1.33K_0402_1%  [R_0402]  205.65 75.2 0 bottom
PRA8  4.7K_0402_1%  [R_0402]  206.56 74.44 180 bottom
PRA9  523_0603_1%  [R_0603]  209.28 73.62 90 bottom
PRB1  0.01_1206_1%  [R_1206_4P-D]  185.86 57.44 180 top
PRB2  1M_0402_5%  [R_0402]  191.58 51.58 180 top
PRB3  3M_0402_5%  [R_0402]  190.66 52.47 0 top
PRB5  4.12K_0603_1%  [R_0603]  175.94 54.5 0 top
PRB6  10_1206_1%  [R_1206]  189.69 60.4 0 bottom
PRB7  2.2_0603_5%  [R_0603]  191.2 55.8 0 bottom
PRB9  4.12K_0603_1%  [R_0603]  183.19 53.75 90 top
PRB10  4.12K_0603_1%  [R_0603]  185.72 55.77 180 top
PRB11  0.01_1206_1%  [R_1206_4P-D]  170.4 58.27 0 bottom
PRB12  4.7_1206_5%  [R_1206]  178.74 52.85 180 top
PRB13  10_0603_1%  [R_0603]  195.6 53.17 270 bottom
PRB14  6.8_0603_1%  [R_0603]  196.82 53.17 270 bottom
PRB15  100K_0402_1%  [R_0402]  196.92 60.81 270 bottom
PRB16  453K_0402_1%  [R_0402]  199.3 53.28 0 bottom
PRB17  422K_0402_1%  [R_0402]  199.22 60.99 270 bottom
PRB18  0_0402_5%  [R0402_0OHM]  199.27 56.62 0 bottom
PRB19  0_0402_5%  [R0402_0OHM]  199.27 55.84 0 bottom
PRB20  100K_0402_1%  [R_0402]  199.31 54.05 0 bottom
PRB21  66.5K_0402_1%  [R_0402]  199.21 59.28 0 bottom
PRB22  0_0402_5%  [R0402_0OHM]  147.2 33.55 0 bottom
PRG1  1_0402_5%  [R_0402]  174.24 87.31 180 bottom
PRG2  2.2_0603_5%  [R_0603]  167.43 89.3 180 bottom
PRG3  0_0603_5%  [R_0603]  165.65 85.75 180 bottom
PRG4  4.7_1206_5%  [R_1206]  162.03 80.22 180 top
PRG6  1.58K_0603_1%  [R_0603]  194.74 82.82 0 bottom
PRG7  3K_0402_1%  [R_0402]  195.77 77.54 180 top
PRG8  10K_0402_1%  [R_0402]  194.85 76.55 270 top
PRG9  1.58K_0603_1%  [R_0603]  197.21 82.94 270 bottom
PRM1  2.2_0603_5%  [R_0603]  9.7 70.76 180 bottom
PRM2  11.5K_0402_1%  [R_0402]  13.56 76.32 90 bottom
PRM3  4.7_1206_5%  [R_1206]  7.44 67.57 180 top
PRM4  5.1_0603_5%  [R_0603]  13.42 71.94 90 bottom
PRM5  5.1_0603_5%  [R_0603]  12.12 71.94 90 bottom
PRM6  6.04K_0402_1%  [R_0402]  6.12 77.3 270 bottom
PRM7  470K_0402_1%  [R_0402]  11.92 79.34 270 bottom
PRM8  0_0402_5%  [R0402_0OHM]  10.14 79.34 270 bottom
PRM9  10K_0402_1%  [R_0402]  5.34 77.31 270 bottom
PRM10  0_0402_5%  [R_0402]  11.03 79.34 270 bottom
PRM11  0_0402_5%  [R_0402]  8.36 79.34 270 bottom
PRM12  0_0402_5%  [R0402_0OHM]  6.59 79.34 270 bottom
PRV1  0_0402_5%  [R0402_0OHM]  125.79 138.32 180 top
PRV3  20K_0402_1%  [R_0402]  125.64 135 0 top
PRV5  1K_0402_5%  [R_0402]  125.64 135.78 0 top
PRV6  0_0402_5%  [R_0402]  126.35 140.43 270 top
PRV7  4.7_1206_5%  [R_1206]  118.03 124.04 180 top
PRV8  20K_0402_1%  [R_0402]  122.03 139.52 90 top
PRV9  2K_0402_1%  [R_0402]  122.92 139.52 90 top
PRV10  20K_0402_1%  [R_0402]  123.81 140.43 270 top
PRV11  18K_0402_1%  [R_0402]  122.41 140.02 90 bottom
PRV12  0_0603_5%  [R_0603]  124.7 133.33 0 top
PRV13  0_0402_5%  [R_0402]  121.39 140.94 270 bottom
PRV14  0_0402_5%  [R_0402]  121.92 132.29 270 top
PRV15  499K_0402_1%  [R_0402]  120.18 138.96 0 top
PRV17  4.7_1206_5%  [R_1206]  117.84 131.53 270 top
PRV18  0_0402_5%  [R_0402]  117.38 139.72 0 top
PRV20  0_0603_5%  [R_0603]  117.97 134.32 270 top
PRV22  10K_0402_5%  [R_0402]  120.3 135.88 90 bottom
PRV24  0_0402_5%  [R_0402]  115.73 137.1 0 top
PRV26  10K_0402_5%  [R_0402]  124.87 137.56 0 top
PRV27  1K_0402_5%  [R_0402]  124.82 139.52 90 top
PRV28  13.7K_0402_1%  [R_0402]  122.92 132.3 270 top
PRV29  0_0402_5%  [R_0402]  118.3 137.1 180 top
PRV30  0_0402_5%  [R_0402]  116.7 136.34 90 bottom
PRV31  0_0402_5%  [R_0402]  117.38 136.34 0 top
PRV32  0_0402_5%  [R_0402]  117.58 136.34 90 bottom
PRV33  147K_0402_1%  [R_0402]  117.58 138.12 90 bottom
PRW1  10K_0402_1%  [R_0402]  194.04 131.9 90 bottom
PRW2  1M_0402_1%  [R_0402]  193.2 132.81 270 bottom
PRW3  0_0402_5%  [R_0402]  190.29 131.9 90 bottom
PRW4  0_0402_5%  [R_0402]  191.05 132.81 270 bottom
PRW5  100K_0402_5%  [R_0402]  191.19 135.08 180 bottom
PRW6  4.7_1206_5%  [R_1206]  183.62 140.36 270 top
PRW7  0_0402_5%  [R0402_0OHM]  186.43 138.83 90 bottom
PRW8  12.7K +-1% 0402  [R_0402]  187.88 132.82 180 bottom
PRW9  10K_0402_1%  [R_0402]  189.53 132.81 270 bottom
PRW10  1K_0402_1%  [R_0402]  188.77 131.9 90 bottom
PRZ1  100_0402_1%  [R_0402]  206.5 69.24 180 bottom
PRZ2  953_0402_1%  [R_0402]  201.15 65.09 90 top
PRZ3  953_0402_1%  [R_0402]  199.42 65.04 0 top
PRZ4  6.8K_0402_1%  [R_0402]  198.56 65.04 180 top
PRZ5  5K_0402_1%  [R_0402]  200.38 67.97 0 top
PRZ6  5K_0402_1%  [R_0402]  200.01 65.86 90 top
PRZ8  10K_0402_1%  [R_0402]  204.78 70.06 180 bottom
PRZ10  95.3K_0402_1%  [R_0402]  204.83 70.94 90 bottom
PRZ11  15.4K_0402_1%  [R_0402]  197.65 65.93 0 top
PRZ13  29.4K_0402_1%  [R_0402]  199.68 75.59 0 top
PRZ14  0_0402_5%  [R_0402]  200.59 76.35 180 top
PRZ15  0_0402_5%  [R0402_0OHM]  206.5 70.06 180 bottom
PRZ17  464_0402_1%  [R_0402]  201.29 68.73 180 top
PRZ18  464_0402_1%  [R_0402]  198.78 67.94 90 top
PRZ19  8.45K_0402_1%  [R_0402]  198.01 67.94 90 top
PRZ20  10K_0402_1%  [R_0402]  201.23 71.27 180 top
PRZ21  100_0402_1%  [R_0402]  204.78 66.57 180 bottom
PRZ22  100_0402_1%  [R_0402]  207.2 71.65 180 bottom
PRZ23  10K_0402_5%  [R_0402]  203.69 76.02 90 bottom
PRZ24  3.9_0402_1%  [R_0402]  204.78 72.66 180 bottom
PRZ25  0_0402_5%  [R0402_0OHM]  202.93 76.02 90 bottom
PRZ26  5.11K_0402_1%  [R_0402]  203.77 63.7 180 bottom
PRZ28  3K_0402_1%  [R_0402]  199.63 68.52 90 top
PRZ29  3K_0402_1%  [R_0402]  197.28 69.6 90 top
PRZ30  2.1K_0402_1%  [R_0402]  196.91 68.85 180 top
PRZ31  0_0402_5%  [R_0402]  199.58 71.27 180 top
PRZ33  18.7K_0402_1%  [R_0402]  203.77 64.46 180 bottom
PRZ35  23.2K_0402_1%  [R_0402]  202.93 65.73 90 bottom
PRZ36  45.3_0402_1%  [R_0402]  200.52 80.36 270 bottom
PRZ38  100_0402_1%  [R_0402]  199.25 80.36 270 bottom
PRZ39  75_0402_1%  [R_0402]  198.36 80.36 270 bottom
PRZ41  100_0402_1%  [R_0402]  204.78 68.41 180 bottom
PRZ43  10K_0402_1%  [R_0402]  200.13 63.82 90 bottom
PRZ45  31.6K_0402_1%  [R_0402]  200.97 65.68 180 bottom
PRZ47  0_0402_5%  [R0402_0OHM]  204.78 67.65 180 bottom
PRZ48  27.4K_0402_1%  [R_0402]  197.85 77.16 90 top
PRZ49  866_0402_1%  [R_0402]  198.74 78.07 270 top
PRZ50  0_0402_5%  [R0402_0OHM]  196.27 79.01 180 bottom
PRZ51  110K_0402_1%  [R_0402]  194.42 66.64 270 bottom
PRZ52  1.65K_0402_1%  [R_0402]  195.31 65.73 90 bottom
PRZ53  4.7_0805_5%  [R_0805]  192.3 68.96 180 bottom
PRZ54  29.4K_0402_1%  [R_0402]  193.53 77.16 90 bottom
PRZ56  10K_0402_1%  [R_0402]  195.36 78.13 0 bottom
PRZ59  100_0402_1%  [R_0402]  196.27 79.9 180 bottom
PRZ63  8.25K_0402_1%  [R_0402]  192.51 70.2 270 top
PRZ64  8.25K_0402_1%  [R_0402]  192.51 71.57 90 top
PRZ65  10_0402_1%  [R_0402]  191.87 71.34 270 bottom
PRZ66  110K_0402_1%  [R_0402]  193.61 74.32 180 bottom
PRZ67  4.53K_0402_1%  [R_0402]  192.51 68.42 270 top
PRZ68  4.7K_0402_1%  [R_0402]  192.51 73.35 90 top
PRZ69  1.65K_0402_1%  [R_0402]  191.83 74.32 180 bottom
PRZ70  11.3K_0402_1%  [R_0402]  193.4 67.51 90 top
PRZ71  19.1K_0402_1%  [R_0402]  193.4 74.26 270 top
PRZ72  0_0402_5%  [R_0402]  195.18 67.89 90 top
PRZ73  11.5K_0402_1%  [R_0402]  193.4 69.29 90 top
PRZ74  4.02K_0402_1%  [R_0402]  193.4 72.49 270 top
PRZ75  0_0402_5%  [R_0402]  195.11 69.74 0 top
PRZ76  2.2_0603_5%  [R_0603]  172.89 67.2 180 bottom
PRZ77  2.2_0603_5%  [R_0603]  173.53 63.39 180 bottom
PRZ79  0_0603_5%  [R_0603]  165.15 66.19 180 bottom
PRZ80  1_0402_5%  [R_0402]  177.3 63.79 0 bottom
PRZ81  1_0402_5%  [R_0402]  177.3 62.99 0 bottom
PRZ82  4.7_1206_5%  [R_1206]  166.99 74.76 270 top
PRZ84  4.7_1206_5%  [R_1206]  161.4 60.79 90 top
PRZ85  2.1K_0603_1%  [R_0603]  189.66 66.39 0 bottom
PRZ87  2.1K_0603_1%  [R_0603]  189.66 65.12 0 bottom
PRZ88  4.22K_0402_1%  [R_0402]  196.25 65.04 0 bottom
PRZ90  4.22K_0402_1%  [R_0402]  194.93 65.88 270 top
PRZ93  0_0402_5%  [R0402_0OHM]  192.72 77.62 180 bottom
PRZ94  0_0402_5%  [R0402_0OHM]  207.2 70.89 180 bottom
PRZ95  0_0402_5%  [R0402_0OHM]  204.78 65.81 180 bottom
PRZ98  49.9_0402_1%  [R_0402]  200.52 77.16 90 bottom
PRZ99  10_0402_1%  [R_0402]  199.25 77.16 90 bottom
PRZ100  100_0402_1%  [R_0402]  198.36 77.16 90 bottom
PRZ102  2.1K_0603_1%  [R_0603]  192.07 66.39 0 bottom
PRZ103  2.1K_0603_1%  [R_0603]  192.07 65.12 0 bottom
PRZ104  10K_0402_1%  [R_0402]  194.98 66.7 0 top
PRZ105  10K_0402_1%  [R_0402]  195.99 67.97 0 top
PRZ106  0_0402_5%  [R_0402]  196.71 64.97 90 top
PRZ107  100_0402_1%  [R_0402]  192.72 76.73 180 bottom
PRZ108  1M_0402_1%  [R_0402]  190.56 65.68 180 top
PRZ109  1M_0402_1%  [R_0402]  190.56 64.92 180 top
PTPM1  PAD  [TPC12]  14.49 78.51 0 bottom
PU301  SY8286BRAC_QFN20_3X3  [SY8284BRAC_QFN20_3X3]  187.74 117.2 270 bottom
PU302  -  [SY8270CTMC_QFN13_4X3]  185.01 105.49 270 bottom
PU1001  JW5068AQFNF-TRPBF_QFN20_3X3  [SY8286RAC_QFN20_3X3]  185.9 96.54 270 bottom
PU1801  -  [SY8032ABC_SOT23-6]  181.78 84.8 180 bottom
PU2501  -  [SY8032ABC_SOT23-6]  6.01 43.86 180 bottom
PUA1  -  [RT9610CGQW_WDFN8_2X2]  166.11 57.23 0 bottom
PUB1  -  [BQ24725ARGRR_QFN20_3P5X3P5]  194.75 58.39 270 bottom
PUG1  -  [RT9610CGQW_WDFN8_2X2]  168.39 86.65 90 bottom
PUM1  -  [G5616BRZ1U_TQFN20_3X3]  7.44 74.35 0 bottom
PUV1  -  [RT8812AGQW_WQFN20_3X3]  123.25 135.02 90 top
PUW1  JW5068AQFNF-TRPBF_QFN20_3X3  [SY8286RAC_QFN20_3X3]  186.54 137.46 270 bottom
PUZ1  -  [RT3602AJGQW_WQFN48_6X6]  200.81 68.93 90 bottom
PUZ2  -  [RT9610CGQW_WDFN8_2X2]  173.66 64.55 90 bottom
PUZ3  -  [RT9610CGQW_WDFN8_2X2]  173.66 60.74 90 bottom
Q9  AO3416L 1N SOT-23  [MMBF170-7-F_SOT23-3]  214.46 21.21 90 bottom
Q21  -  [EM5209VF_DFN14_3X2]  184.01 68.65 0 bottom
Q4108  -  [2N7002K_SOT23-3]  25.19 101.55 180 bottom
Q5001  L2N7002SDW1T1G 2N SC88-6  [DMN65D8LDW-7_SOT363-6]  144.72 35.47 270 bottom
QA2  -  [MMBT3904WH_SOT323-3]  27.2 45.67 270 top
QC1  L2N7002SDW1T1G 2N SC88-6  [2N7002DWH_SOT363-6]  80.99 22.54 0 bottom
QC7  L2N7002SDW1T1G 2N SC88-6  [2N7002DWH_SOT363-6]  85.98 20.94 180 bottom
QG1  L2N7002SDW1T1G 2N SC88-6  [2N7002KDW_SOT363-6]  19.27 127.11 0 top
QG2  L2N7002SDW1T1G 2N SC88-6  [2N7002DWH_SOT363-6]  16.76 130.49 180 top
QG4  2N7002K_SOT23-3  [2N7002_SOT23-3]  176.79 125.12 270 top
QS1  2N7002KW_SOT323-3  [SSM3K7002FU_SC70-3]  178.33 42.33 0 bottom
QU3  2N7002K_SOT23-3  [2N7002_SOT23-3]  7.91 89.07 180 bottom
QV2  L2N7002SDW1T1G 2N SC88-6  [2N7002KDWH_SOT363-6]  162.88 91.3 90 bottom
QV3  -  [2N7002K_SOT23-3]  176.79 129.94 270 top
QV5  AO3416L 1N SOT-23-3  [LBSS138LT1G_SOT23-3]  127.85 120.54 90 bottom
QV20  PJ2301 1P SOT23-3  [PJ2301_SOT23-3]  188.47 125.12 270 top
QV26  PJ2301 1P SOT23-3  [PJ2301_SOT23-3]  188.35 130.92 270 top
QV30  L2N7002SDW1T1G 2N SC88-6  [2N7002DW-7-F_SOT363-6]  194.82 126.7 180 top
QV50  2N7002W-T/R7_SOT323-3  [2N7002W-T-R7_SOT323-3]  173.76 123.21 270 bottom
QV146  2N7002K_SOT23-3  [2N7002_SOT23-3]  129.93 124.61 270 bottom
QWL1  PJ2301 1P SOT23-3  [PJ2301_SOT23-3]  249.92 25.32 0 bottom
QWL2  2N7002KW_SOT323-3  [SSM3K7002FU_SC70-3]  227.82 19.58 270 top
R23  100K_0402_5%  [R_0402]  212.71 21.31 270 bottom
R24  0_0603_5%  [R_0603]  211.69 19.77 90 bottom
R28  0_0402_5%  [R_0402]  150.91 26.18 0 top
R126  4.7K_0402_5%  [R_0402]  16.94 133.95 270 top
R163  100K_0201_5%  [R_0201]  119.11 41.21 270 top
R166  33_0402_5%  [R_0402]  63.66 102.76 0 top
R170  0_0201_5%  [R_0201]  80.06 103.61 90 bottom
R171  0_0201_5%  [R_0201]  80.69 103.61 90 bottom
R173  0_0201_5%  [R_0201]  79.8 99.8 90 bottom
R201  0_0603_5%  [R0603_0OHM]  260.86 11.15 270 top
R202  0_0603_5%  [R0603_0OHM]  259.65 11.15 270 top
R203  1K_0402_5%  [R_0402]  199.63 35.5 90 top
R207  549_0402_1%  [R_0402]  202.42 35.5 90 top
R215  100K_0402_5%  [R_0402]  27.67 99.77 90 bottom
R259  0_0201_5%  [R0201_0OHM]  118.85 42.98 270 top
R295  1K_0402_5%  [R_0402]  150.33 43.35 180 bottom
R1088  0_0402_5%  [R_0402]  90.79 42.32 270 bottom
R1089  0_0402_5%  [R_0402]  92.18 42.32 270 bottom
R5092  100K_0402_1%  [R_0402]  142.63 37.43 270 bottom
R5093  22_0402_1%  [R_0402]  143.52 36.77 0 bottom
R5094  0_0201_5%  [R0201_0OHM]  197.67 59.9 90 bottom
R5175  0_0201_5%  [R_0201]  80.44 99.8 90 bottom
R5176  10K_0402_5%  [R_0402]  63.61 103.69 90 top
R5178  0_0201_5%  [R0201_0OHM]  163.01 28.47 0 bottom
R5179  100P_0402_50V8J  [C_0402]  230.03 2.68 0 top
R5180  0.1U_0402_25V6  [C_0402]  227.77 2.18 180 top
R5187  0_0402_5%  [R_0402]  58.53 104.62 270 top
R5201  100K_0402_5%  [R_0402]  67.99 110.59 270 top
R5202  0_0402_5%  [R_0402]  150.91 25.17 0 top
R5260  0_0201_5%  [R_0201]  28.22 44.85 180 top
R5261  0_0402_5%  [R0402_0OHM]  237.14 20.85 0 bottom
R5262  0_0402_5%  [R0402_0OHM]  237.14 21.61 0 bottom
R5263  0_0201_5%  [R_0201]  248.32 18.49 0 bottom
R5264  0_0201_5%  [R_0201]  248.32 17.85 0 bottom
R5265  0_0201_5%  [R_0201]  86.01 24.57 270 top
R5266  0_0201_5%  [R_0201]  85.38 24.57 270 top
R5267  0_0201_5%  [R_0201]  83.68 24.57 270 top
R5268  0_0201_5%  [R_0201]  84.31 24.57 270 top
R5269  0_0201_5%  [R_0201]  141.96 34.54 270 bottom
R5270  0_0201_5%  [R_0201]  90.93 29.57 270 bottom
R5271  0_0201_5%  [R_0201]  83.76 22.3 270 bottom
R5272  0_0201_5%  [R_0201]  86.27 24 180 bottom
R5273  1K_0402_5%  [R_0402]  228.41 17.93 180 top
RA1  0_0402_5%  [R_0402]  23.11 46.5 270 top
RA2  0_0402_5%  [R_0402]  16.5 44.29 0 top
RA4  0_0402_5%  [R_0402]  11.3 34.5 0 top
RA5  0_0402_5%  [R_0402]  27.96 32.85 180 top
RA6  0_0402_5%  [R_0402]  12.18 37.94 0 top
RA7  0_0402_5%  [R_0402]  25.98 29.85 90 top
RA8  0_0402_5%  [R_0402]  29.53 35.07 90 top
RA9  100K_0402_5%  [R_0402]  23.1 42.64 0 top
RA10  10K_0402_0.5%  [R_0402]  24.07 46.53 270 top
RA13  0_0402_5%  [R_0402]  17.85 30.4 270 top
RA14  0_0402_5%  [R_0402]  19.24 30.4 270 top
RA15  0_0402_5%  [R_0402]  21.15 30.4 270 top
RA16  47K_0402_5%  [R_0402]  13.85 42.71 270 top
RA17  20K_0402_5%  [R_0402]  14.74 41.8 90 top
RA23  0_0402_5%  [R_0402]  13.1 37.18 180 top
RA24  100K_0402_5%  [R_0402]  14.81 31.75 90 top
RA26  22_0402_5%  [R_0402]  18.48 42.69 90 top
RA33  0_0603_5%  [R0603_0OHM]  26.17 38.32 0 top
RA34  0_0603_5%  [R0603_0OHM]  26.17 40.86 0 top
RA35  0_0603_5%  [R0603_0OHM]  26.17 37.05 0 top
RA36  0_0603_5%  [R0603_0OHM]  26.17 39.59 0 top
RA37  30_0402_1%  [R_0402]  18.61 32.68 270 top
RA38  30_0402_1%  [R_0402]  19.37 32.68 270 top
RA39  0_0402_5%  [R_0402]  27.41 43.73 180 top
RA40  2.2K_0402_5%  [R_0402]  17.85 31.77 90 top
RA41  100K_0402_1%  [R_0402]  12.18 38.7 0 top
RA42  200K_0402_1%  [R_0402]  14.89 38.88 0 top
RA51  0_0603_5%  [R0603_0OHM-NPM]  19.06 38.47 180 bottom
RA52  0_0603_5%  [R0603_0OHM-NPM]  19.06 36.9 180 bottom
RA53  22_0402_5%  [R_0402]  20.51 43.6 270 top
RA54  0_0603_5%  [R0603_0OHM-NPM]  19.16 36.66 270 bottom
RC1  24.9_0402_1%  [R_0402]  124.16 68 270 top
RC2  1K_0402_5%  [R_0402]  129.14 59.71 180 bottom
RC3  1K_0402_5%  [R_0402]  132.36 88 270 top
RC4  499_0201_1%  [R_0201]  130.26 78.31 270 bottom
RC5  49.9_0402_1%  [R_0402]  101.09 53.85 90 top
RC6  49.9_0402_1%  [R_0402]  100.33 53.85 90 top
RC14  51_0402_5%  [R_0402]  133 76.98 0 bottom
RC32  470_0402_5%  [R_0402]  85.33 39.31 90 top
RC38  121_0402_1%  [R_0402]  104.44 53.85 90 top
RC39  80.6_0402_1%  [R_0402]  103.68 53.85 90 top
RC40  100_0402_1%  [R_0402]  102.92 53.85 90 top
RC49  499_0201_1%  [R_0201]  116.31 42.98 270 top
RC50  499_0201_1%  [R_0201]  115.68 42.98 270 top
RC51  1K_0201_5%  [R_0201]  99.17 39.36 270 bottom
RC72  20K_0402_5%  [R_0402]  230.03 16.62 0 bottom
RC76  200_0402_1%  [R_0402]  104.38 41.85 90 top
RC77  0_0201_5%  [R_0201]  100.67 53.28 0 bottom
RC81  10K_0402_5%  [R_0402]  85.75 21.69 270 top
RC82  10K_0402_5%  [R_0402]  84.03 20.81 0 top
RC91  20K_0201_5%  [R_0201]  92.57 36.62 90 bottom
RC92  200K_0402_1%  [R_0402]  129.9 43.47 270 bottom
RC93  20K_0201_5%  [R_0201]  90.53 36.62 90 bottom
RC94  1M_0201_5%  [R_0201]  89.9 36.62 90 bottom
RC96  60.4_0402_1%  [R_0402]  130.59 45.87 0 bottom
RC98  10M_0402_5%  [R_0402]  105.84 38.23 180 bottom
RC100  1K_0201_5%  [R_0201]  96.76 34.65 90 bottom
RC101  100K_0201_5%  [R_0201]  86.47 35.72 270 top
RC102  1K_0402_5%  [R_0402]  129.05 66.67 270 bottom
RC103  10K_0201_5%  [R_0201]  100.31 42.65 90 top
RC104  1K_0201_5%  [R_0201]  101.11 50.12 180 bottom
RC105  10K_0201_5%  [R_0201]  105.9 42.4 90 top
RC106  10K_0201_5%  [R_0201]  101.11 49.36 180 bottom
RC107  8.2K_0201_5%  [R_0201]  102.22 43.24 270 top
RC108  0_0201_5%  [R0201_0OHM]  99.41 48.3 180 bottom
RC109  0_0201_5%  [R0201_0OHM]  98.93 52.65 180 bottom
RC110  0_0201_5%  [R0201_0OHM]  97.65 43.24 270 top
RC113  1K_0402_5%  [R_0402]  128.99 60.48 90 bottom
RC115  10K_0201_5%  [R_0201]  99.68 42.65 90 top
RC116  60.4_0402_1%  [R_0402]  128.16 61.4 270 bottom
RC117  100K_0201_5%  [R_0201]  100.15 45.17 0 bottom
RC118  4.7K_0201_5%  [R_0201]  107.17 39.86 90 top
RC119  113_0402_1%  [R_0402]  125.97 42.64 270 top
RC120  100_0402_1%  [R_0402]  125.54 43.58 180 top
RC122  8.2K_0201_5%  [R_0201]  108.44 40.44 270 top
RC123  100K_0201_5%  [R_0201]  118.22 42.4 90 top
RC124  100K_0201_5%  [R_0201]  119.49 42.4 90 top
RC127  10K_0201_5%  [R_0201]  100.82 37.52 270 bottom
RC128  10K_0201_5%  [R_0201]  100.82 36.25 270 bottom
RC132  150_0201_1%  [R_0201]  108.19 38.74 135 bottom
RC142  20K_0402_1%  [R_0402]  144.46 38.5 90 top
RC150  0_0402_5%  [R_0402]  112.28 54.27 0 top
RC154  0_0402_5%  [R_0402]  99.17 40.1 270 top
RC165  10K_0201_5%  [R_0201]  107.17 41.13 90 top
RC173  0_0402_5%  [R_0402]  87.92 35.64 0 top
RC179  56_0402_5%  [R_0402]  129.93 75.41 270 bottom
RC180  220_0402_5%  [R_0402]  129.1 75.41 270 bottom
RC181  100_0402_1%  [R_0402]  130.01 76.22 180 bottom
RC183  20K_0201_5%  [R_0201]  230.41 11.37 0 bottom
RC185  49.9_0402_1%  [R_0402]  124.02 74.02 0 top
RC187  4.7K_0201_5%  [R_0201]  100.95 41.38 90 top
RC188  0_0402_5%  [R_0402]  116.19 95.85 270 top
RC189  0_0805_5%  [R0805_0OHM]  106.24 97.49 180 top
RC190  0_0805_5%  [R0805_0OHM]  106.23 93.96 180 top
RC191  0_0805_5%  [R0805_0OHM]  106.23 95.72 180 top
RC193  1K_0402_1%  [R_0402]  129.33 84.8 90 bottom
RC201  150K_0201_5%  [R_0201]  107.81 39.86 90 top
RC215  10K_0402_5%  [R_0402]  80.25 20.26 90 top
RC216  10K_0402_5%  [R_0402]  80.25 22.83 270 top
RC218  1K_0201_5%  [R_0201]  114.32 41.8 180 top
RC226  10K_0201_5%  [R_0201]  116.95 42.98 270 top
RC227  200_0201_1%  [R_0201]  116.73 39.33 180 bottom
RC230  0_0201_5%  [R0201_0OHM]  98.92 53.42 180 bottom
RC357  1K_0201_5%  [R_0201]  125.17 34.74 90 bottom
RC360  10K_0201_5%  [R_0201]  115.01 41.17 0 top
RC369  15_0402_5%  [R_0402]  150.3 45.96 180 bottom
RC374  10K_0201_5%  [R_0201]  117.58 42.98 270 top
RC379  150K_0201_5%  [R_0201]  101.18 46.63 180 bottom
RC380  10K_0201_5%  [R_0201]  115.01 41.8 0 top
RC381  10K_0201_5%  [R_0201]  103.49 43.24 270 top
RC382  10K_0201_5%  [R_0201]  124.1 39.56 270 top
RC383  100K_0201_5%  [R_0201]  98.53 40.63 270 bottom
RC384  100K_0201_5%  [R_0201]  99.17 40.63 270 bottom
RC388  0_0402_5%  [R_0402]  127.49 42.64 270 top
RC389  51_0402_5%  [R_0402]  128.1 87.09 90 top
RC390  51_0402_5%  [R_0402]  125.62 87.09 90 top
RC391  51_0402_5%  [R_0402]  130.64 87.09 90 top
RC393  1K_0402_5%  [R_0402]  127.28 88 270 top
RC398  51_0402_1%  [R_0402]  124.8 87.09 90 top
RC399  51_0402_5%  [R_0402]  129.83 87.1 180 top
RC401  75K_0201_5%  [R_0201]  116.82 34.14 90 bottom
RC402  0_0402_5%  [R_0402]  125.08 42.64 270 top
RC403  20K_0201_5%  [R_0201]  117.36 39.33 0 bottom
RC404  10K_0201_5%  [R_0201]  117.94 38.69 180 bottom
RC409  10K_0201_5%  [R_0201]  101.18 46 180 bottom
RC410  10K_0201_5%  [R_0201]  124.1 37.76 90 top
RC421  0_0402_5%  [R_0402]  124.02 74.78 0 top
RC427  0_0805_5%  [R_0805]  143.37 43.11 90 top
RC429  100K_0402_5%  [R_0402]  115.25 96.79 180 bottom
RC434  100K_0201_5%  [R_0201]  92.16 25.05 270 top
RC447  33_0402_5%  [R_0402]  129.12 44.51 270 bottom
RC448  33_0402_5%  [R_0402]  129.12 41.88 90 bottom
RC456  49.9_0402_1%  [R_0402]  126.94 36.84 90 bottom
RC457  33_0402_5%  [R_0402]  96.33 44.22 180 bottom
RC459  33_0201_5%  [R_0201]  97.26 54.35 270 bottom
